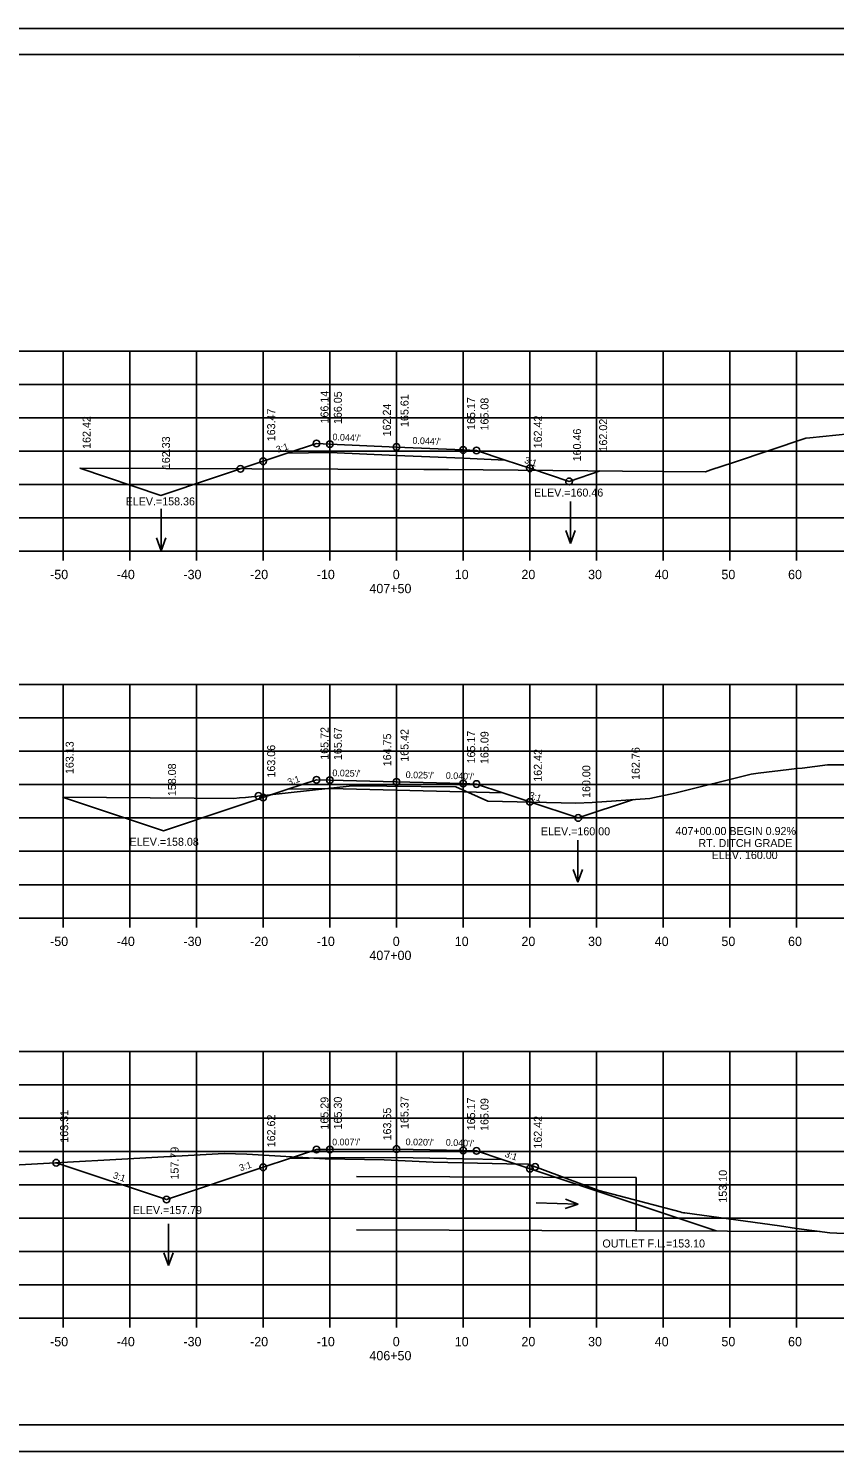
# Model space of a CAD drawing. Extents: x 1368503 to 1373085, y 379840 to 381833.
# Drawn here: x 1372866.9 to 1372987.8, y 380815 to 381028.3 of the extents above; entities that cross this region are included whole.
import ezdxf

# ---------------------------------------------------------------- set-up
doc = ezdxf.new("R2010")
doc.units = 0
for name, color, linetype in [('S_BREAKLINE', 7, 'Continuous'), ('S_BRIDGE', 7, 'Continuous'), ('S_EDGE_PAVEMENT', 7, 'Continuous'), ('S_GRAVEL_ROAD', 7, 'Continuous'), ('S_MISC_BOUNDARY', 7, 'Continuous'), ('S_OBSCURES', 7, 'Continuous'), ('S_PHOTO_CENTERS', 7, 'Continuous'), ('S_PHOTO_NOTES', 7, 'Continuous'), ('S_RDW_PT_SYM', 7, 'Continuous'), ('S_SHOULDER', 7, 'Continuous'), ('S_STREAM_ANNOT', 7, 'Continuous'), ('S_TRAILS', 7, 'Continuous'), ('S_TRAILS_ANNOT', 7, 'Continuous')]:
    doc.layers.add(name, color=color, linetype=linetype)

msp = doc.modelspace()

# ---------------------------------------------------------------- linework, layer by layer
at = {"layer": 'S_BREAKLINE'}
for p, q in [((1372916.1, 380856.23), (1372958.05, 380856.07)), ((1372958.05, 380848.07), (1372958.05, 380856.07)), ((1372916.1, 380848.23), (1372985.61, 380847.97))]:
    msp.add_line(p, q, dxfattribs=at)
at = {"layer": 'S_BRIDGE'}
for p, q in [((1372764.08, 381024.42), (1373080.26, 381024.42)), ((1372916.6, 381024.16), (1372916.6, 381024.16)), ((1372916.6, 381024.16), (1372916.6, 381024.16)), ((1373080.26, 380818.96), (1372764.08, 380818.96))]:
    msp.add_line(p, q, dxfattribs=at)
at = {"layer": 'S_EDGE_PAVEMENT'}
for p, q in [((1372782.08, 380949.96), (1373062.08, 380949.96)), ((1372872.08, 380948.56), (1372872.08, 380949.96)), ((1372882.08, 380948.56), (1372882.08, 380949.96)), ((1372892.08, 380948.56), (1372892.08, 380949.96)), ((1372902.08, 380948.56), (1372902.08, 380949.96)), ((1372912.08, 380948.56), (1372912.08, 380949.96)), ((1372922.08, 380948.56), (1372922.08, 380949.96)), ((1372932.08, 380948.56), (1372932.08, 380949.96)), ((1372942.08, 380948.56), (1372942.08, 380949.96)), ((1372952.08, 380948.56), (1372952.08, 380949.96)), ((1372962.08, 380948.56), (1372962.08, 380949.96)), ((1372972.08, 380948.56), (1372972.08, 380949.96)), ((1372982.08, 380948.56), (1372982.08, 380949.96)), ((1372782.08, 380894.96), (1373062.08, 380894.96)), ((1372872.08, 380893.56), (1372872.08, 380894.96)), ((1372882.08, 380893.56), (1372882.08, 380894.96)), ((1372892.08, 380893.56), (1372892.08, 380894.96)), ((1372902.08, 380893.56), (1372902.08, 380894.96)), ((1372912.08, 380893.56), (1372912.08, 380894.96)), ((1372922.08, 380893.56), (1372922.08, 380894.96)), ((1372932.08, 380893.56), (1372932.08, 380894.96)), ((1372942.08, 380893.56), (1372942.08, 380894.96)), ((1372952.08, 380893.56), (1372952.08, 380894.96)), ((1372962.08, 380893.56), (1372962.08, 380894.96)), ((1372972.08, 380893.56), (1372972.08, 380894.96)), ((1372982.08, 380893.56), (1372982.08, 380894.96)), ((1372782.08, 380834.96), (1373062.08, 380834.96)), ((1372872.08, 380833.56), (1372872.08, 380834.96)), ((1372882.08, 380833.56), (1372882.08, 380834.96)), ((1372892.08, 380833.56), (1372892.08, 380834.96)), ((1372902.08, 380833.56), (1372902.08, 380834.96)), ((1372912.08, 380833.56), (1372912.08, 380834.96)), ((1372922.08, 380833.56), (1372922.08, 380834.96)), ((1372932.08, 380833.56), (1372932.08, 380834.96)), ((1372942.08, 380833.56), (1372942.08, 380834.96)), ((1372952.08, 380833.56), (1372952.08, 380834.96)), ((1372962.08, 380833.56), (1372962.08, 380834.96)), ((1372972.08, 380833.56), (1372972.08, 380834.96)), ((1372982.08, 380833.56), (1372982.08, 380834.96))]:
    msp.add_line(p, q, dxfattribs=at)
at = {"layer": 'S_GRAVEL_ROAD'}
for p, q in [((1372948.17, 380957.4), (1372948.17, 380951.12)), ((1372886.8, 380956.3), (1372886.8, 380950.02)), ((1372948.17, 380951.12), (1372947.47, 380953.04)), ((1372948.17, 380951.12), (1372948.87, 380953.04)), ((1372886.8, 380950.02), (1372886.1, 380951.94)), ((1372886.8, 380950.02), (1372887.5, 380951.94)), ((1372949.26, 380906.62), (1372949.26, 380900.34)), ((1372949.26, 380900.34), (1372948.56, 380902.26)), ((1372949.26, 380900.34), (1372949.96, 380902.26)), ((1372949.32, 380852.06), (1372947.42, 380852.83)), ((1372943.04, 380852.27), (1372949.32, 380852.06)), ((1372949.32, 380852.06), (1372947.38, 380851.43)), ((1372887.87, 380849.14), (1372887.87, 380842.85)), ((1372887.87, 380842.85), (1372887.17, 380844.78)), ((1372887.87, 380842.85), (1372888.57, 380844.78))]:
    msp.add_line(p, q, dxfattribs=at)
at = {"layer": 'S_MISC_BOUNDARY'}
for points in [[(1372874.56, 380962.39), (1372926.18, 380962.19), (1372929.87, 380962.19), (1372955.96, 380961.96), (1372968.41, 380961.85), (1372969.23, 380962.17), (1372972.62, 380963.25), (1372983.46, 380966.91), (1372984.08, 380966.97), (1372991.9, 380967.76), (1373001.26, 380968), (1373002.33, 380968.03), (1373003.31, 380968), (1373012.26, 380967.78), (1373013.5, 380967.81), (1373017.38, 380967.91), (1373020.09, 380967.8), (1373025.07, 380967.29), (1373038.31, 380963.23), (1373041.27, 380963.09), (1373042.79, 380962.9), (1373044.93, 380963.46), (1373047.57, 380963.07), (1373062.08, 380964.52)], [(1372872, 380913.09), (1372891.73, 380912.92), (1372897.66, 380912.86), (1372898.52, 380912.97), (1372899.44, 380913.05), (1372915.42, 380914.76), (1372930.99, 380914.65), (1372935.77, 380912.48), (1372948.98, 380912.19), (1372951.41, 380912.27), (1372960.1, 380912.9), (1372963.81, 380913.7), (1372975.29, 380916.51), (1372976.32, 380916.67), (1372980.91, 380917.22), (1372982.11, 380917.37), (1372982.93, 380917.43), (1372986.73, 380917.91), (1372990.95, 380917.91)], [(1372856.45, 380857.48), (1372896.24, 380859.65), (1372899.64, 380859.55), (1372911.36, 380858.88), (1372920.25, 380858.71), (1372927.59, 380858.34), (1372938.65, 380858.11), (1372941.83, 380858.05), (1372952.41, 380854.12), (1372964.63, 380850.92), (1372964.87, 380850.84), (1372965.14, 380850.78), (1372965.15, 380850.78), (1372965.35, 380850.78), (1372979.51, 380848.8), (1372982.1, 380848.44), (1372987.1, 380847.77), (1372994.58, 380847.44)]]:
    msp.add_lwpolyline(points, dxfattribs=at)
at = {"layer": 'S_OBSCURES'}
for points in [[(1372938.4, 380963.61), (1372932.08, 380963.88), (1372922.08, 380964.32), (1372912.08, 380964.76), (1372905.68, 380964.63)], [(1372938.04, 380913.73), (1372932.08, 380913.88), (1372922.08, 380914.14), (1372912.08, 380914.39), (1372905.8, 380914.26)], [(1372937.94, 380858.77), (1372932.08, 380858.88), (1372922.08, 380859.08), (1372912.08, 380859.02), (1372906.01, 380858.89)]]:
    msp.add_lwpolyline(points, dxfattribs=at)
at = {"layer": 'S_PHOTO_CENTERS'}
for p, q in [((1372782.08, 380979.96), (1373062.08, 380979.96)), ((1372782.08, 380979.96), (1373062.08, 380979.96)), ((1372872.08, 380949.96), (1372872.08, 380979.96)), ((1372872.08, 380949.96), (1372872.08, 380979.96)), ((1372882.08, 380949.96), (1372882.08, 380979.96)), ((1372882.08, 380949.96), (1372882.08, 380979.96)), ((1372892.08, 380949.96), (1372892.08, 380979.96)), ((1372892.08, 380949.96), (1372892.08, 380979.96)), ((1372902.08, 380949.96), (1372902.08, 380979.96)), ((1372902.08, 380949.96), (1372902.08, 380979.96)), ((1372912.08, 380949.96), (1372912.08, 380979.96)), ((1372912.08, 380949.96), (1372912.08, 380979.96)), ((1372922.08, 380949.96), (1372922.08, 380979.96)), ((1372922.08, 380949.96), (1372922.08, 380979.96)), ((1372932.08, 380949.96), (1372932.08, 380979.96)), ((1372932.08, 380949.96), (1372932.08, 380979.96)), ((1372942.08, 380949.96), (1372942.08, 380979.96)), ((1372942.08, 380949.96), (1372942.08, 380979.96)), ((1372952.08, 380949.96), (1372952.08, 380979.96)), ((1372952.08, 380949.96), (1372952.08, 380979.96)), ((1372962.08, 380949.96), (1372962.08, 380979.96)), ((1372962.08, 380949.96), (1372962.08, 380979.96)), ((1372972.08, 380949.96), (1372972.08, 380979.96)), ((1372972.08, 380949.96), (1372972.08, 380979.96)), ((1372982.08, 380949.96), (1372982.08, 380979.96)), ((1372982.08, 380949.96), (1372982.08, 380979.96)), ((1372782.08, 380974.96), (1373062.08, 380974.96)), ((1372782.08, 380974.96), (1373062.08, 380974.96)), ((1372782.08, 380969.96), (1373062.08, 380969.96)), ((1372782.08, 380969.96), (1373062.08, 380969.96)), ((1372782.08, 380964.96), (1373062.08, 380964.96)), ((1372782.08, 380964.96), (1373062.08, 380964.96)), ((1372782.08, 380959.96), (1373062.08, 380959.96)), ((1372782.08, 380959.96), (1373062.08, 380959.96)), ((1372782.08, 380954.96), (1373062.08, 380954.96)), ((1372782.08, 380954.96), (1373062.08, 380954.96)), ((1372782.08, 380949.96), (1373062.08, 380949.96)), ((1372782.08, 380949.96), (1373062.08, 380949.96)), ((1372782.08, 380929.96), (1373062.08, 380929.96)), ((1372872.08, 380894.96), (1372872.08, 380929.96)), ((1372882.08, 380894.96), (1372882.08, 380929.96)), ((1372892.08, 380894.96), (1372892.08, 380929.96)), ((1372902.08, 380894.96), (1372902.08, 380929.96)), ((1372912.08, 380894.96), (1372912.08, 380929.96)), ((1372922.08, 380894.96), (1372922.08, 380929.96)), ((1372932.08, 380894.96), (1372932.08, 380929.96)), ((1372942.08, 380894.96), (1372942.08, 380929.96)), ((1372952.08, 380894.96), (1372952.08, 380929.96)), ((1372962.08, 380894.96), (1372962.08, 380929.96)), ((1372972.08, 380894.96), (1372972.08, 380929.96)), ((1372982.08, 380894.96), (1372982.08, 380929.96)), ((1372782.08, 380924.96), (1373062.08, 380924.96)), ((1372782.08, 380919.96), (1373062.08, 380919.96)), ((1372782.08, 380914.96), (1373062.08, 380914.96)), ((1372782.08, 380909.96), (1373062.08, 380909.96)), ((1372782.08, 380904.96), (1373062.08, 380904.96)), ((1372782.08, 380899.96), (1373062.08, 380899.96)), ((1372782.08, 380894.96), (1373062.08, 380894.96)), ((1372782.08, 380874.96), (1373062.08, 380874.96)), ((1372872.08, 380834.96), (1372872.08, 380874.96)), ((1372882.08, 380834.96), (1372882.08, 380874.96)), ((1372892.08, 380834.96), (1372892.08, 380874.96)), ((1372902.08, 380834.96), (1372902.08, 380874.96)), ((1372912.08, 380834.96), (1372912.08, 380874.96)), ((1372922.08, 380834.96), (1372922.08, 380874.96)), ((1372932.08, 380834.96), (1372932.08, 380874.96)), ((1372942.08, 380834.96), (1372942.08, 380874.96)), ((1372952.08, 380834.96), (1372952.08, 380874.96)), ((1372962.08, 380834.96), (1372962.08, 380874.96)), ((1372972.08, 380834.96), (1372972.08, 380874.96)), ((1372982.08, 380834.96), (1372982.08, 380874.96)), ((1372782.08, 380869.96), (1373062.08, 380869.96)), ((1372782.08, 380864.96), (1373062.08, 380864.96)), ((1372782.08, 380859.96), (1373062.08, 380859.96)), ((1372782.08, 380854.96), (1373062.08, 380854.96)), ((1372782.08, 380849.96), (1373062.08, 380849.96)), ((1372782.08, 380844.96), (1373062.08, 380844.96)), ((1372782.08, 380839.96), (1373062.08, 380839.96)), ((1372782.08, 380834.96), (1373062.08, 380834.96))]:
    msp.add_line(p, q, dxfattribs=at)
at = {"layer": 'S_PHOTO_NOTES'}
for p, q in [((1372751.68, 381028.32), (1373085.01, 381028.32)), ((1372952.65, 380961.99), (1372947.96, 380960.42)), ((1372957.62, 380912.72), (1372949.35, 380909.96)), ((1372751.68, 380814.98), (1373085.01, 380814.98))]:
    msp.add_line(p, q, dxfattribs=at)
for points in [[(1372751.67, 381028.32), (1373085.01, 381028.32), (1373085.01, 380814.98), (1372751.67, 380814.98)], [(1372998, 381024.42), (1372998, 381014.54), (1373033.73, 381014.54), (1373033.73, 381011.62), (1373056.93, 381011.62), (1373056.93, 380987.29), (1373080.26, 380987.29), (1373080.26, 380818.96), (1372764.08, 380818.96), (1372764.08, 381024.42)]]:
    msp.add_lwpolyline(points, close=True, dxfattribs=at)
for centre in [(1372910.08, 380966.1), (1372912.08, 380966.01), (1372922.08, 380965.57), (1372932.08, 380965.13), (1372934.08, 380965.05), (1372902.08, 380963.43), (1372898.66, 380962.29), (1372942.08, 380962.38), (1372947.96, 380960.42), (1372910.08, 380915.69), (1372912.08, 380915.64), (1372922.08, 380915.39), (1372932.08, 380915.13), (1372934.08, 380915.05), (1372901.37, 380913.26), (1372902.08, 380913.02), (1372942.08, 380912.39), (1372949.35, 380909.96), (1372910.08, 380860.25), (1372912.08, 380860.27), (1372922.08, 380860.33), (1372932.08, 380860.13), (1372934.08, 380860.05), (1372871.03, 380858.28), (1372902.08, 380857.59), (1372942.08, 380857.39), (1372942.89, 380857.66), (1372887.59, 380852.76)]:
    msp.add_circle(centre, 0.5, dxfattribs=at)
at = {"layer": 'S_STREAM_ANNOT'}
for points in [[(1372874.56, 380962.39), (1372886.75, 380958.32), (1372902.08, 380963.43), (1372905.68, 380964.63), (1372910.08, 380966.1), (1372912.08, 380966.01), (1372922.08, 380965.57), (1372932.08, 380965.13), (1372934.08, 380965.05), (1372938.4, 380963.61), (1372942.08, 380962.38), (1372947.96, 380960.42), (1372952.65, 380961.99)], [(1372872, 380913.09), (1372887.15, 380908.04), (1372905.8, 380914.26), (1372910.08, 380915.69), (1372912.08, 380915.64), (1372922.08, 380915.39), (1372932.08, 380915.13), (1372934.08, 380915.05), (1372938.04, 380913.73), (1372942.08, 380912.39), (1372949.35, 380909.96), (1372957.62, 380912.72)], [(1372871.03, 380858.28), (1372887.59, 380852.76), (1372902.08, 380857.59), (1372906.01, 380858.89), (1372910.08, 380860.25), (1372912.08, 380860.27), (1372922.08, 380860.33), (1372932.08, 380860.13), (1372934.08, 380860.05), (1372937.94, 380858.77), (1372970.05, 380848.06)]]:
    msp.add_lwpolyline(points, dxfattribs=at)

# ---------------------------------------------------------------- texts
at = {"layer": 'S_GRAVEL_ROAD'}
for s, p in [('ELEV.=160.46', (1372942.7, 380958.14)), ('ELEV.=158.36', (1372881.45, 380956.82)), ('ELEV.=160.00', (1372943.73, 380907.36)), ('407+00.00 BEGIN 0.92%', (1372963.94, 380907.4)), ('ELEV.=158.08', (1372882.03, 380905.79)), ('RT. DITCH GRADE', (1372967.37, 380905.6)), ('ELEV. 160.00', (1372969.35, 380903.8)), ('ELEV.=157.79', (1372882.51, 380850.58)), ('OUTLET F.L.=153.10', (1372952.97, 380845.57))]:
    msp.add_text(s, height=1.2, dxfattribs=at).set_placement(p)
at = {"layer": 'S_RDW_PT_SYM'}
for s, rotation, p in [('3:1', 18.4344, (1372904.21, 380964.67)), ("0.044'/'", 357.4812, (1372912.46, 380966.6)), ("0.044'/'", 357.4812, (1372924.46, 380966.07)), ('3:1', 341.5658, (1372941.18, 380963.21)), ("0.025'/'", 358.5569, (1372912.45, 380916.23)), ("0.025'/'", 358.5569, (1372923.45, 380915.95)), ("0.040'/'", 357.7094, (1372929.46, 380915.84)), ('3:1', 18.4349, (1372905.92, 380914.83)), ('3:1', 341.5659, (1372941.87, 380912.98)), ("0.007'/'", 0.3846, (1372912.43, 380860.87)), ("0.020'/'", 358.8542, (1372923.44, 380860.91)), ("0.040'/'", 357.7094, (1372929.46, 380860.84)), ('3:1', 341.5651, (1372938.24, 380859.19)), ('3:1', 341.5668, (1372879.47, 380855.99)), ('3:1', 18.4338, (1372898.68, 380856.98))]:
    msp.add_text(s, height=1, rotation=rotation, dxfattribs=at).set_placement(p)
at = {"layer": 'S_SHOULDER'}
for s, p in [('166.14', (1372911.88, 380969.1)), ('166.05', (1372913.88, 380969.01)), ('165.61', (1372923.88, 380968.57)), ('165.17', (1372933.88, 380968.13)), ('165.08', (1372935.88, 380968.05)), ('162.42', (1372876.2, 380965.29)), ('163.47', (1372903.88, 380966.43)), ('162.42', (1372943.88, 380965.38)), ('160.46', (1372949.76, 380963.42)), ('162.02', (1372953.68, 380964.9)), ('162.33', (1372888.1, 380962.25)), ('165.72', (1372911.88, 380918.69)), ('165.67', (1372913.88, 380918.64)), ('165.42', (1372923.88, 380918.39)), ('165.17', (1372933.88, 380918.13)), ('165.09', (1372935.88, 380918.05)), ('163.13', (1372873.65, 380916.54)), ('163.06', (1372903.88, 380916.02)), ('162.42', (1372943.88, 380915.39)), ('162.76', (1372958.56, 380915.66)), ('158.08', (1372889.01, 380913.23)), ('160.00', (1372951.15, 380912.96)), ('165.29', (1372911.88, 380863.25)), ('165.30', (1372913.88, 380863.27)), ('165.37', (1372923.88, 380863.33)), ('165.17', (1372933.88, 380863.13)), ('165.09', (1372935.88, 380863.05)), ('163.31', (1372872.83, 380861.28)), ('162.62', (1372903.88, 380860.59)), ('162.42', (1372943.88, 380860.39)), ('157.79', (1372889.39, 380855.76)), ('153.10', (1372971.63, 380852.29))]:
    msp.add_text(s, height=1.2, rotation=90, dxfattribs=at).set_placement(p)
at = {"layer": 'S_TRAILS'}
for s, p in [('-50', (1372870.12, 380945.76)), ('-40', (1372880.12, 380945.76)), ('-30', (1372890.12, 380945.76)), ('-20', (1372900.12, 380945.76)), ('-10', (1372910.12, 380945.76)), ('0', (1372921.52, 380945.76)), ('10', (1372930.82, 380945.76)), ('20', (1372940.82, 380945.76)), ('30', (1372950.82, 380945.76)), ('40', (1372960.82, 380945.76)), ('50', (1372970.82, 380945.76)), ('60', (1372980.82, 380945.76)), ('407+50', (1372918.02, 380943.66)), ('-50', (1372870.12, 380890.76)), ('-40', (1372880.12, 380890.76)), ('-30', (1372890.12, 380890.76)), ('-20', (1372900.12, 380890.76)), ('-10', (1372910.12, 380890.76)), ('0', (1372921.52, 380890.76)), ('10', (1372930.82, 380890.76)), ('20', (1372940.82, 380890.76)), ('30', (1372950.82, 380890.76)), ('40', (1372960.82, 380890.76)), ('50', (1372970.82, 380890.76)), ('60', (1372980.82, 380890.76)), ('407+00', (1372918.02, 380888.66)), ('-50', (1372870.12, 380830.76)), ('-40', (1372880.12, 380830.76)), ('-30', (1372890.12, 380830.76)), ('-20', (1372900.12, 380830.76)), ('-10', (1372910.12, 380830.76)), ('0', (1372921.52, 380830.76)), ('10', (1372930.82, 380830.76)), ('20', (1372940.82, 380830.76)), ('30', (1372950.82, 380830.76)), ('40', (1372960.82, 380830.76)), ('50', (1372970.82, 380830.76)), ('60', (1372980.82, 380830.76)), ('406+50', (1372918.02, 380828.66))]:
    msp.add_text(s, height=1.4, dxfattribs=at).set_placement(p)
at = {"layer": 'S_TRAILS_ANNOT'}
for s, p in [('162.24', (1372921.23, 380967.17)), ('164.75', (1372921.28, 380917.71)), ('163.65', (1372921.28, 380861.62))]:
    msp.add_text(s, height=1.2, rotation=90, dxfattribs=at).set_placement(p)

doc.saveas('drawing.dxf')
